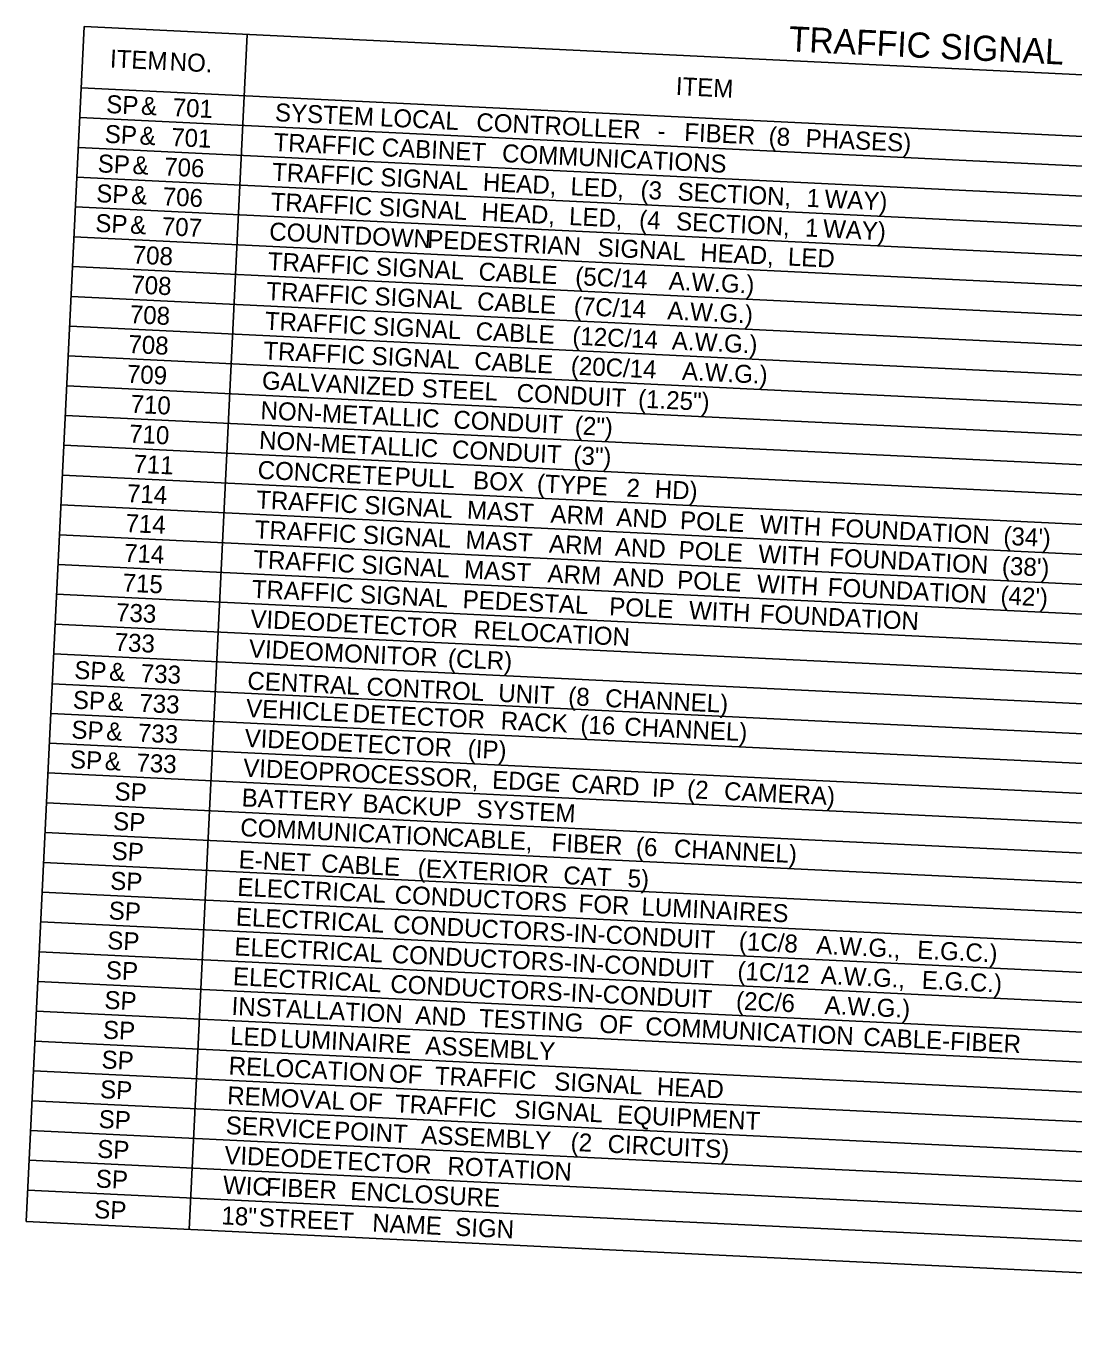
# Model space of a CAD drawing. Extents: x 668933 to 670801, y 741155 to 743955.
# Drawn here: x 669100.3 to 669245.8, y 743471 to 743652.8 of the extents above; entities that cross this region are included whole.
import ezdxf

# ---------------------------------------------------------------- set-up
doc = ezdxf.new("R2010")
doc.units = 0
doc.layers.add('R_Dimension', color=7, linetype='Continuous')

msp = doc.modelspace()

# ---------------------------------------------------------------- linework, layer by layer
at = {"layer": 'R_Dimension'}
for p, q in [((669100.31, 743486.68), (669108.37, 743652.72)), ((669108.37, 743652.72), (669432.18, 743637)), ((669122.95, 743485.58), (669131.01, 743651.62)), ((669107.96, 743644.2), (669431.76, 743628.48)), ((669107.76, 743640.06), (669431.56, 743624.34)), ((669107.56, 743635.92), (669431.36, 743620.2)), ((669107.35, 743631.78), (669431.16, 743616.06)), ((669107.15, 743627.65), (669430.96, 743611.92)), ((669106.95, 743623.51), (669430.76, 743607.78)), ((669106.75, 743619.37), (669430.56, 743603.64)), ((669106.55, 743615.23), (669430.36, 743599.51)), ((669106.35, 743611.09), (669430.16, 743595.37)), ((669106.15, 743606.95), (669429.95, 743591.23)), ((669105.95, 743602.81), (669429.75, 743587.09)), ((669105.75, 743598.67), (669429.55, 743582.95)), ((669105.55, 743594.54), (669429.35, 743578.81)), ((669105.34, 743590.4), (669429.15, 743574.67)), ((669105.14, 743586.26), (669428.95, 743570.53)), ((669104.94, 743582.12), (669428.75, 743566.39)), ((669104.74, 743577.98), (669428.55, 743562.26)), ((669104.54, 743573.84), (669428.35, 743558.12)), ((669104.34, 743569.7), (669428.15, 743553.98)), ((669104.14, 743565.56), (669427.94, 743549.84)), ((669103.94, 743561.42), (669427.74, 743545.7)), ((669103.74, 743557.29), (669427.54, 743541.56)), ((669103.54, 743553.15), (669427.34, 743537.42)), ((669103.33, 743549.01), (669427.14, 743533.28)), ((669103.13, 743544.87), (669426.94, 743529.14)), ((669102.93, 743540.73), (669426.74, 743525.01)), ((669102.73, 743536.59), (669426.54, 743520.87)), ((669102.53, 743532.45), (669426.34, 743516.73)), ((669102.33, 743528.31), (669426.14, 743512.59)), ((669102.13, 743524.17), (669425.93, 743508.45)), ((669101.93, 743520.04), (669425.73, 743504.31)), ((669101.73, 743515.9), (669425.53, 743500.17)), ((669101.53, 743511.76), (669425.33, 743496.03)), ((669101.32, 743507.62), (669425.13, 743491.89)), ((669101.12, 743503.48), (669424.93, 743487.76)), ((669100.92, 743499.34), (669424.73, 743483.62)), ((669100.72, 743495.2), (669424.53, 743479.48)), ((669100.52, 743491.06), (669424.33, 743475.34)), ((669100.31, 743486.68), (669424.11, 743470.96))]:
    msp.add_line(p, q, dxfattribs=at)

# ---------------------------------------------------------------- texts
for s, height, p in [('TRAFFIC', 3.5, (669206.16, 743649.27)), (' SIGNAL', 3.5, (669225.9, 743648.31)), ('ITEM', 2.5, (669111.9, 743647.03)), (' NO.', 2.5, (669119.26, 743646.67)), ('ITEM', 2.5, (669190.49, 743643.21)), ('SP', 2.5, (669111.38, 743640.71)), (' &', 2.5, (669115.29, 743640.52)), (' 701', 2.5, (669119.68, 743640.31)), ('SYSTEM', 2.5, (669134.82, 743639.57)), (' LOCAL', 2.5, (669148.47, 743638.91)), (' CONTROLLER', 2.5, (669161.86, 743638.26)), (' FIBER', 2.5, (669190.74, 743636.86)), ('SP', 2.5, (669111.18, 743636.57)), (' &', 2.5, (669115.09, 743636.38)), (' 701', 2.5, (669119.48, 743636.17)), ('TRAFFIC', 2.5, (669134.62, 743635.43)), (' -', 2.5, (669187.02, 743637.04)), (' (8', 2.5, (669202.46, 743636.29)), (' PHASES)', 2.5, (669207.59, 743636.04)), (' CABINET', 2.5, (669148.72, 743634.75)), (' COMMUNICATIONS', 2.5, (669165.43, 743633.94)), ('SP', 2.5, (669110.2, 743632.47)), (' &', 2.5, (669114.11, 743632.28)), (' 706', 2.5, (669118.5, 743632.07)), ('TRAFFIC', 2.5, (669134.42, 743631.29)), (' SIGNAL', 2.5, (669148.52, 743630.61)), (' HEAD,', 2.5, (669162.77, 743629.92)), ('SP', 2.5, (669110, 743628.33)), (' &', 2.5, (669113.91, 743628.14)), (' 706', 2.5, (669118.3, 743627.93)), (' LED,', 2.5, (669174.94, 743629.33)), (' (3', 2.5, (669184.67, 743628.85)), (' SECTION,', 2.5, (669189.81, 743628.6)), (' 1', 2.5, (669207.72, 743627.73)), (' WAY)', 2.5, (669210.22, 743627.61)), ('TRAFFIC', 2.5, (669134.22, 743627.15)), (' SIGNAL', 2.5, (669148.32, 743626.47)), (' HEAD,', 2.5, (669162.57, 743625.78)), ('SP', 2.5, (669109.87, 743624.19)), (' &', 2.5, (669113.78, 743624)), (' LED,', 2.5, (669174.74, 743625.19)), (' (4', 2.5, (669184.47, 743624.71)), (' SECTION,', 2.5, (669189.61, 743624.47)), (' 707', 2.5, (669118.17, 743623.79)), ('COUNTDOWN', 2.5, (669134.02, 743623.02)), (' 1', 2.5, (669207.52, 743623.6)), (' WAY)', 2.5, (669210.01, 743623.47)), (' PEDESTRIAN', 2.5, (669155.04, 743622)), (' SIGNAL', 2.5, (669178.71, 743620.85)), ('708', 2.5, (669115.06, 743619.79)), ('TRAFFIC', 2.5, (669133.82, 743618.88)), (' HEAD,', 2.5, (669192.96, 743620.15)), (' LED', 2.5, (669205.13, 743619.56)), (' SIGNAL', 2.5, (669147.91, 743618.19)), (' CABLE', 2.5, (669162.17, 743617.5)), (' (5C/14', 2.5, (669175.6, 743616.85)), ('708', 2.5, (669114.86, 743615.65)), (' A.W.G.)', 2.5, (669188.59, 743616.22)), ('TRAFFIC', 2.5, (669133.61, 743614.74)), (' SIGNAL', 2.5, (669147.71, 743614.05)), (' CABLE', 2.5, (669161.97, 743613.36)), ('708', 2.5, (669114.66, 743611.51)), (' (7C/14', 2.5, (669175.4, 743612.71)), (' A.W.G.)', 2.5, (669188.39, 743612.08)), ('TRAFFIC', 2.5, (669133.41, 743610.6)), (' SIGNAL', 2.5, (669147.51, 743609.91)), (' CABLE', 2.5, (669161.77, 743609.22)), (' (12C/14', 2.5, (669175.2, 743608.57)), (' A.W.G.)', 2.5, (669189.02, 743607.9)), ('708', 2.5, (669114.46, 743607.37)), ('TRAFFIC', 2.5, (669133.21, 743606.46)), (' SIGNAL', 2.5, (669147.31, 743605.78)), (' CABLE', 2.5, (669161.57, 743605.08)), (' (20C/14', 2.5, (669174.99, 743604.43)), ('709', 2.5, (669114.25, 743603.23)), ('GALVANIZED', 2.5, (669133.01, 743602.32)), (' A.W.G.)', 2.5, (669190.43, 743603.68)), (' STEEL', 2.5, (669154.27, 743601.29)), (' CONDUIT', 2.5, (669167.46, 743600.65)), ('710', 2.5, (669114.76, 743599.06)), (' (1.25")', 2.5, (669184.33, 743599.83)), ('NON-METALLIC', 2.5, (669132.81, 743598.18)), (' CONDUIT', 2.5, (669158.67, 743596.93)), ('710', 2.5, (669114.56, 743594.92)), (' (2")', 2.5, (669175.54, 743596.11)), ('NON-METALLIC', 2.5, (669132.61, 743594.04)), (' CONDUIT', 2.5, (669158.47, 743592.79)), (' (3")', 2.5, (669175.34, 743591.97)), ('711', 2.5, (669115.17, 743590.74)), ('CONCRETE', 2.5, (669132.41, 743589.9)), (' PULL', 2.5, (669150.5, 743589.03)), (' BOX', 2.5, (669161.41, 743588.5)), (' (TYPE', 2.5, (669170.28, 743588.07)), ('714', 2.5, (669114.26, 743586.64)), ('TRAFFIC', 2.5, (669132.21, 743585.77)), (' 2', 2.5, (669182.72, 743587.46)), (' HD)', 2.5, (669186.64, 743587.27)), (' SIGNAL', 2.5, (669146.31, 743585.08)), (' MAST', 2.5, (669160.56, 743584.39)), ('714', 2.5, (669114.06, 743582.5)), (' ARM', 2.5, (669172.16, 743583.83)), (' AND', 2.5, (669181.3, 743583.38)), (' POLE', 2.5, (669190.15, 743582.95)), (' WITH', 2.5, (669201.22, 743582.41)), ('TRAFFIC', 2.5, (669132.01, 743581.63)), (' SIGNAL', 2.5, (669146.1, 743580.94)), (' FOUNDATION', 2.5, (669211.07, 743581.94)), (" (34')", 2.5, (669235.06, 743580.77)), (' MAST', 2.5, (669160.36, 743580.25)), (' ARM', 2.5, (669171.96, 743579.69)), (' AND', 2.5, (669181.1, 743579.24)), (' POLE', 2.5, (669189.95, 743578.81)), ('714', 2.5, (669113.86, 743578.36)), ('TRAFFIC', 2.5, (669131.81, 743577.49)), (' SIGNAL', 2.5, (669145.9, 743576.8)), (' WITH', 2.5, (669201.02, 743578.28)), (' FOUNDATION', 2.5, (669210.87, 743577.8)), (" (38')", 2.5, (669234.86, 743576.63)), (' MAST', 2.5, (669160.16, 743576.11)), (' ARM', 2.5, (669171.76, 743575.55)), (' AND', 2.5, (669180.9, 743575.1)), ('715', 2.5, (669113.66, 743574.22)), ('TRAFFIC', 2.5, (669131.6, 743573.35)), (' POLE', 2.5, (669189.75, 743574.67)), (' WITH', 2.5, (669200.82, 743574.14)), (' FOUNDATION', 2.5, (669210.67, 743573.66)), (' SIGNAL', 2.5, (669145.7, 743572.66)), (' PEDESTAL', 2.5, (669159.96, 743571.97)), (" (42')", 2.5, (669234.66, 743572.49)), ('733', 2.5, (669112.75, 743570.12)), (' POLE', 2.5, (669180.31, 743570.98)), (' WITH', 2.5, (669191.38, 743570.45)), (' FOUNDATION', 2.5, (669201.23, 743569.97)), ('VIDEO', 2.5, (669131.4, 743569.21)), (' DETECTOR', 2.5, (669140.9, 743568.75)), (' RELOCATION', 2.5, (669161.47, 743567.75)), ('733', 2.5, (669112.55, 743565.98)), ('VIDEO', 2.5, (669131.2, 743565.07)), (' MONITOR', 2.5, (669140.7, 743564.61)), ('SP', 2.5, (669106.95, 743562.1)), (' (CLR)', 2.5, (669157.92, 743563.77)), (' &', 2.5, (669110.86, 743561.91)), (' 733', 2.5, (669115.25, 743561.7)), ('CENTRAL', 2.5, (669130.99, 743560.61)), (' CONTROL', 2.5, (669146.6, 743559.85)), (' UNIT', 2.5, (669164.9, 743558.96)), (' (8', 2.5, (669174.62, 743558.49)), ('SP', 2.5, (669106.75, 743557.96)), (' &', 2.5, (669110.66, 743557.77)), (' 733', 2.5, (669115.05, 743557.56)), ('VEHICLE', 2.5, (669130.8, 743556.79)), (' CHANNEL)', 2.5, (669179.75, 743558.24)), (' DETECTOR', 2.5, (669144.68, 743556.12)), (' RACK', 2.5, (669165.25, 743555.12)), ('SP', 2.5, (669106.55, 743553.82)), (' &', 2.5, (669110.46, 743553.63)), (' 733', 2.5, (669114.85, 743553.42)), (' (16', 2.5, (669176.32, 743554.58)), (' CHANNEL)', 2.5, (669182.41, 743554.29)), ('VIDEO', 2.5, (669130.6, 743552.65)), (' DETECTOR', 2.5, (669140.1, 743552.19)), (' (IP)', 2.5, (669160.66, 743551.2)), ('SP', 2.5, (669106.35, 743549.68)), (' &', 2.5, (669110.26, 743549.49)), (' 733', 2.5, (669114.65, 743549.28)), ('VIDEO', 2.5, (669130.4, 743548.52)), (' PROCESSOR,', 2.5, (669139.9, 743548.05)), (' EDGE', 2.5, (669164.06, 743546.88)), (' CARD', 2.5, (669175.05, 743546.35)), (' IP', 2.5, (669186.26, 743545.8)), ('SP', 2.5, (669112.54, 743545.23)), ('BATTERY', 2.5, (669130.2, 743544.38)), (' (2', 2.5, (669191.13, 743545.57)), (' CAMERA)', 2.5, (669196.27, 743545.32)), (' BACKUP', 2.5, (669146.05, 743543.61)), (' SYSTEM', 2.5, (669161.89, 743542.84)), ('SP', 2.5, (669112.34, 743541.1)), ('COMMUNICATION', 2.5, (669130, 743540.24)), (' CABLE,', 2.5, (669157.78, 743538.89)), ('SP', 2.5, (669112.14, 743536.96)), (' FIBER', 2.5, (669172.31, 743538.18)), (' (6', 2.5, (669184.03, 743537.61)), (' CHANNEL)', 2.5, (669189.3, 743537.36)), ('E-NET', 2.5, (669129.78, 743535.78)), (' CABLE', 2.5, (669140.3, 743535.27)), (' (EXTERIOR', 2.5, (669153.73, 743534.62)), (' CAT', 2.5, (669173.94, 743533.63)), (' 5)', 2.5, (669182.87, 743533.2)), ('SP', 2.5, (669111.94, 743532.82)), ('ELECTRICAL', 2.5, (669129.6, 743531.96)), (' CONDUCTORS', 2.5, (669150.52, 743530.94)), (' FOR', 2.5, (669176.06, 743529.7)), ('SP', 2.5, (669111.73, 743528.68)), ('ELECTRICAL', 2.5, (669129.39, 743527.82)), (' LUMINAIRES', 2.5, (669184.79, 743529.28)), (' CONDUCTORS-IN-CONDUIT', 2.5, (669150.31, 743526.81)), ('SP', 2.5, (669111.53, 743524.54)), (' (1C/8', 2.5, (669198.33, 743524.47)), ('ELECTRICAL', 2.5, (669129.19, 743523.68)), (' CONDUCTORS-IN-CONDUIT', 2.5, (669150.11, 743522.67)), (' A.W.G.,', 2.5, (669209.08, 743523.95)), (' E.G.C.)', 2.5, (669223.1, 743523.27)), ('SP', 2.5, (669111.33, 743520.4)), (' (1C/12', 2.5, (669198.13, 743520.34)), ('ELECTRICAL', 2.5, (669128.99, 743519.54)), (' CONDUCTORS-IN-CONDUIT', 2.5, (669149.91, 743518.53)), (' A.W.G.,', 2.5, (669209.71, 743519.77)), (' E.G.C.)', 2.5, (669223.73, 743519.09)), ('SP', 2.5, (669111.13, 743516.26)), ('INSTALLATION', 2.5, (669128.79, 743515.41)), (' (2C/6', 2.5, (669197.93, 743516.2)), (' A.W.G.)', 2.5, (669210.23, 743515.6)), (' AND', 2.5, (669153.39, 743514.21)), (' TESTING', 2.5, (669162.24, 743513.78)), ('SP', 2.5, (669110.93, 743512.12)), ('LED', 2.5, (669128.59, 743511.27)), (' OF', 2.5, (669178.95, 743512.97)), (' COMMUNICATION', 2.5, (669185.32, 743512.66)), (' LUMINAIRE', 2.5, (669134.63, 743510.97)), (' ASSEMBLY', 2.5, (669154.78, 743509.99)), (' CABLE-FIBER', 2.5, (669215.6, 743511.19)), ('SP', 2.5, (669110.73, 743507.98)), ('RELOCATION', 2.5, (669128.39, 743507.13)), (' OF', 2.5, (669149.72, 743506.09)), (' TRAFFIC', 2.5, (669156.09, 743505.78)), (' SIGNAL', 2.5, (669172.69, 743504.98)), (' HEAD', 2.5, (669186.94, 743504.28)), ('SP', 2.5, (669110.53, 743503.85)), ('REMOVAL', 2.5, (669128.19, 743502.99)), (' OF', 2.5, (669144.19, 743502.21)), (' TRAFFIC', 2.5, (669150.56, 743501.9)), (' SIGNAL', 2.5, (669167.16, 743501.1)), (' EQUIPMENT', 2.5, (669181.41, 743500.4)), ('SP', 2.5, (669110.33, 743499.71)), ('SERVICE', 2.5, (669127.99, 743498.85)), (' POINT', 2.5, (669142.1, 743498.16)), (' ASSEMBLY', 2.5, (669154.22, 743497.58)), ('SP', 2.5, (669110.13, 743495.57)), (' (2', 2.5, (669174.96, 743496.57)), (' CIRCUITS)', 2.5, (669180.09, 743496.32)), ('VIDEO', 2.5, (669127.79, 743494.71)), (' DETECTOR', 2.5, (669137.28, 743494.25)), (' ROTATION', 2.5, (669157.85, 743493.25)), ('SP', 2.5, (669109.93, 743491.43)), ('WIC', 2.5, (669127.59, 743490.57)), (' FIBER', 2.5, (669132.64, 743490.33)), (' ENCLOSURE', 2.5, (669144.36, 743489.76)), ('SP', 2.5, (669109.72, 743487.17)), ('18"', 2.5, (669127.38, 743486.31)), (' STREET', 2.5, (669131.64, 743486.1)), (' NAME', 2.5, (669147.41, 743485.34)), (' SIGN', 2.5, (669158.92, 743484.78))]:
    msp.add_text(s, height=height, rotation=357.2199, dxfattribs=at).set_placement(p)

doc.saveas('drawing.dxf')
